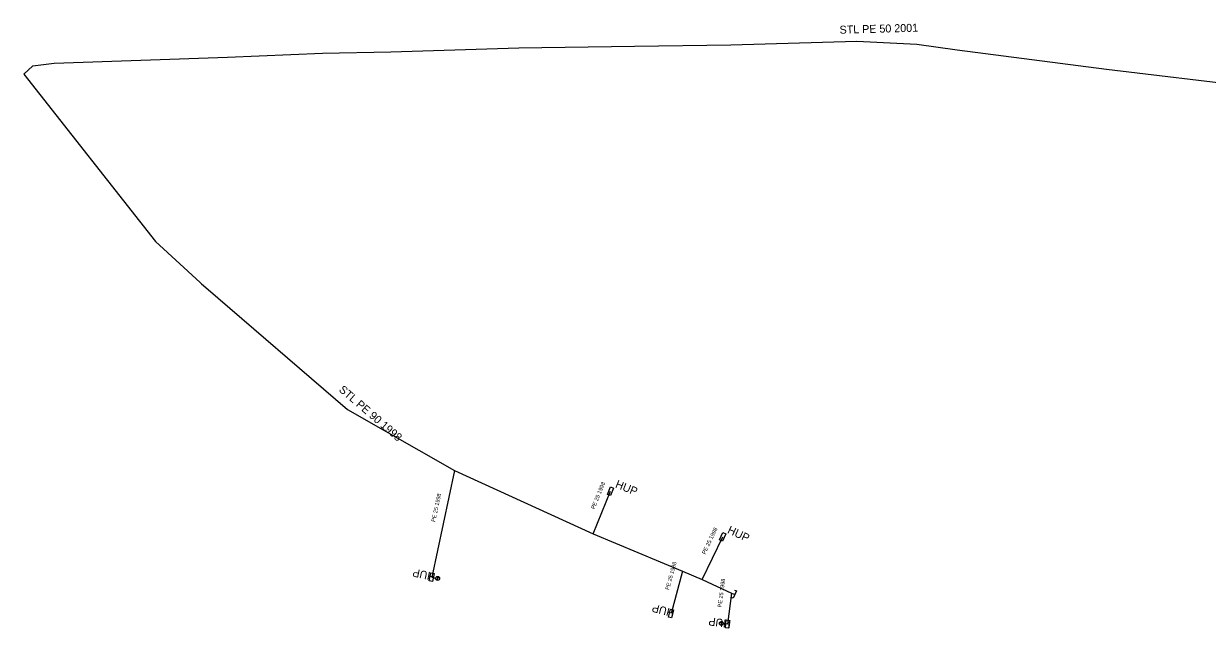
# Model space of a CAD drawing. Extents: x -741240 to -740302, y -1028024 to -1027535.
# Drawn here: x -740989 to -740841.1, y -1027648.1 to -1027572.6 of the extents above; entities that cross this region are included whole.
import ezdxf

# ---------------------------------------------------------------- set-up
doc = ezdxf.new("R2010")
doc.units = 0
for name, color, linetype in [('ST Úsek p_ípojky - provoz', 7, 'Continuous'), ('ST Úsek plynovodu - provoz', 7, 'Continuous'), ('ST_HUP_22_23_popis', 7, 'Continuous'), ('Vrstva 1', 7, 'Continuous')]:
    doc.layers.add(name, color=color, linetype=linetype)

msp = doc.modelspace()

# ---------------------------------------------------------------- linework, layer by layer
at = {"layer": 'ST Úsek p_ípojky - provoz'}
for points in [[(-740935.18, -1027628.4), (-740938.02, -1027641.73)], [(-740917.82, -1027636.33), (-740915.66, -1027630.99)], [(-740904.2, -1027642.03), (-740901.65, -1027636.67)], [(-740906.67, -1027640.97), (-740908.1, -1027646.28)], [(-740900.55, -1027643.71), (-740901.06, -1027647.59)]]:
    msp.add_lwpolyline(points, dxfattribs=at)
at = {"layer": 'ST Úsek plynovodu - provoz'}
for points in [[(-740989.01, -1027578.89), (-740987.88, -1027577.86), (-740985.2, -1027577.52), (-740963.53, -1027576.78), (-740951.66, -1027576.28), (-740943.13, -1027576.13), (-740927.11, -1027575.63), (-740912.67, -1027575.42), (-740900.63, -1027575.23), (-740884.87, -1027574.8), (-740877.38, -1027575.17), (-740872.34, -1027575.88), (-740853.69, -1027578.27), (-740835.56, -1027580.46), (-740820.8, -1027582.43), (-740807.82, -1027584.22), (-740807.32, -1027584.22), (-740786.98, -1027587.02), (-740786.95, -1027587.02), (-740785.34, -1027587.29)], [(-740989.01, -1027578.89), (-740972.54, -1027599.79), (-740966.97, -1027604.91), (-740966.78, -1027605.09), (-740966.26, -1027605.54), (-740948.52, -1027620.77), (-740935.18, -1027628.4), (-740917.82, -1027636.33), (-740906.67, -1027640.97), (-740904.2, -1027642.03), (-740900.55, -1027643.71), (-740900.14, -1027643.9)]]:
    msp.add_lwpolyline(points, dxfattribs=at)
at = {"layer": 'Vrstva 1'}
for p, q in [((-740938.02, -1027641.73), (-740937.53, -1027641.83)), ((-740901.06, -1027647.59), (-740901.56, -1027647.53))]:
    msp.add_line(p, q, dxfattribs=at)
for points in [[(-740915.66, -1027630.45), (-740915.29, -1027630.6), (-740915.66, -1027631.53), (-740916.03, -1027631.38)], [(-740901.62, -1027636.13), (-740901.26, -1027636.3), (-740901.68, -1027637.21), (-740902.04, -1027637.04)], [(-740937.93, -1027642.26), (-740938.32, -1027642.18), (-740938.11, -1027641.2), (-740937.72, -1027641.28)], [(-740908.04, -1027646.81), (-740908.42, -1027646.71), (-740908.16, -1027645.74), (-740907.78, -1027645.85)], [(-740900.92, -1027648.11), (-740901.32, -1027648.06), (-740901.2, -1027647.07), (-740900.8, -1027647.12)]]:
    msp.add_lwpolyline(points, close=True, dxfattribs=at)
msp.add_lwpolyline([(-740900.16, -1027643.34), (-740899.93, -1027643.45), (-740900.35, -1027644.35), (-740900.58, -1027644.25)], dxfattribs=at)
for centre, radius in [((-740937.28, -1027641.88), 0.249), ((-740937.32, -1027641.98), 0.0614), ((-740937.27, -1027641.78), 0.0614), ((-740901.81, -1027647.5), 0.249), ((-740901.81, -1027647.61), 0.0614), ((-740901.78, -1027647.4), 0.0614)]:
    msp.add_circle(centre, radius, dxfattribs=at)

# ---------------------------------------------------------------- texts
at = {"layer": 'ST Úsek p_ípojky - provoz'}
for rotation, p in [(67.9769, (-740917.67, -1027633.29)), (77.9728, (-740937.58, -1027634.86)), (64.5528, (-740903.83, -1027638.92)), (74.935, (-740908.35, -1027643.36)), (82.5263, (-740901.8, -1027645.52))]:
    msp.add_text('PE 25 1998', height=0.5, rotation=rotation, dxfattribs=at).set_placement(p)
at = {"layer": 'ST Úsek plynovodu - provoz'}
for s, rotation, p in [('STL PE 50 2001', 1.5629, (-740887.03, -1027573.86)), ('STL PE 90 1998', 319.3482, (-740949.7, -1027618.44))]:
    msp.add_text(s, height=1, rotation=rotation, dxfattribs=at).set_placement(p)
at = {"layer": 'ST_HUP_22_23_popis'}
for rotation, p in [(338, (-740915.16, -1027630.49)), (335, (-740901.15, -1027636.17)), (168, (-740937.52, -1027641.23)), (165, (-740907.6, -1027645.78)), (173, (-740900.56, -1027647.09))]:
    msp.add_text('HUP', height=1, rotation=rotation, dxfattribs=at).set_placement(p)

doc.saveas('drawing.dxf')
